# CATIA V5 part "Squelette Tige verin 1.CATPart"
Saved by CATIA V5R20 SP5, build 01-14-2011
Part number: Squelette Tige verin 1
Bounding box of the stored display mesh (mm): x -200 to -145.521, y -113.62 to -100, z -70 to -10
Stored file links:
  U:\CFAO\Thinkmotion\Squelette Tige verin 1.CATPart
  U:\CFAO\Thinkmotion\Bras Articule.CATProduct
  U:\CFAO\Thinkmotion\Squelette general.CATPart
  U:\CFAO\Thinkmotion\Squelette Bielle principale.CATPart
  U:\CFAO\Thinkmotion\Squelette Corps verin 1.CATPart
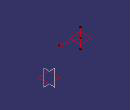
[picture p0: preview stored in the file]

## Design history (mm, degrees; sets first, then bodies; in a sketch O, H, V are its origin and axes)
Set1
  Line1: type Normal, RefPoint Point1, RefSkin Plane2, Start -30, End 30
  Line2: type PtPt, FirstPoint Point1, SecondPoint Point2
  Plane1: type OffsetPt, RefPlane xy-plane, RefPoint Point1
Set2
  Plane2: linked copy from another document
  Point1: linked copy from another document
  Point2: linked copy from another document
Body1 (main body)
